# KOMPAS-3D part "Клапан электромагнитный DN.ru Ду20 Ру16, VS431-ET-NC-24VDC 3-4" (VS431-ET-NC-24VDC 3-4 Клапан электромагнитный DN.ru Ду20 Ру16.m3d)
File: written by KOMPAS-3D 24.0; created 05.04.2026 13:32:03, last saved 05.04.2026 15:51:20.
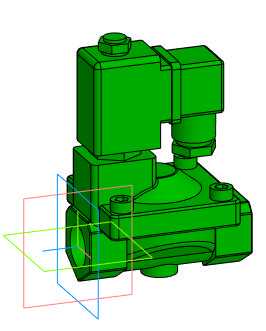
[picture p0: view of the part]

Document properties: Автор: artio; Полное имя файла: VS431-ET-NC-24VDC 3-4 Клапан электромагнитный DN.ru Ду20 Ру16.cdw

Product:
- Body: Тело 1  | qty 1
    Масса: 1.198355
- Part/product: Клапан электромагнитный DN.ru Ду20 Ру16  | designation VS431-ET-NC-24VDC 3-4
    Масса: 0.907
    Раздел спецификации: Прочие изделия
    Форматы листов документа: A3
    Примечание: D130-04741
    additional columns: ef56311e-7521-43dc-8291-0e6108b3d81d; artio; c; Шероховатость не задана; Да

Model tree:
1. Операция без истории:1

Expressions: VS431-ET-NC-24VDC 3-4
